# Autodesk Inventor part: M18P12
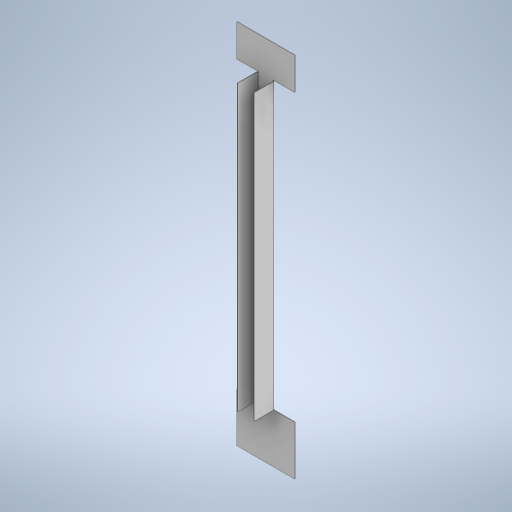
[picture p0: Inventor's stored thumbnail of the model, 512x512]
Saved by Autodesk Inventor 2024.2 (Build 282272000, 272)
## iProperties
Created: 2024-05
Part Number: M18P12
Material: Generic
Document SubType Name: Sheet Metal
Designer: Olivier St-Arneault
Density: 1 g/cm^3
Sheet Metal Rule: Default
Appearance: Default
Author: Olivier St-Arneault
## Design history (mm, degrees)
node "Face1"
  sketch "Sketch1"
    geometry: L1 (-26.987, 171.45)-(-26.987, 141.287); L2 (-26.987, 171.45)-(26.988, 171.45); L3 (26.988, 171.45)-(26.987, 141.287); L4 (26.987, 141.287)-(7.937, 141.287); L5 (-26.987, 141.287)-(-7.937, 141.287); L6 (-7.937, 141.287)-(-7.937, 140.875); L7 (7.937, 141.287)-(7.937, 140.875); L8 (-7.937, -125.413)-(-26.987, -125.413); L9 (7.938, -125.413)-(26.988, -125.413); L10 (-26.987, -125.413)-(-26.987, -171.45); L11 (-26.987, -171.45)-(26.988, -171.45); L12 (26.988, -171.45)-(26.988, -125.413); L13 (-39.175, 0)-(65.281, 0); L14 (0, 44.939)-(0, -395.251); L15 (-7.937, 140.875)-(-7.937, -125.413); L16 (7.938, -125.413)-(7.937, 140.875); 1 further point
    constraints: 32 end point, 6 vertical, 4 perpendicular, 3 horizontal, 2 point on line, 1 collinear, 1 other
    dimensions: "d0" = 30.1625 distance of L1.start L1.end; "d1" = 53.975 distance of L1.start L2.end; "d2" = 19.05 distance of L1.end L5.end; "d3" = 0.41275 distance of L5.end L6.end; "d11" = 342.9 distance between parallel lines of L2 L11; "d12" = 30.1625 distance between parallel lines of L4 L2; "d14" = 19.05 distance of L3.end L4.end; "d26" = 266.7 distance between parallel lines of L4 L9
node "Flange1"
body "Solid1"
face "Plate1" dims "d15" = 0.508 (= Thickness)
sketch "Sketch3"
  geometry: L1 (-266.192, 0)-(-0.508, 0); L2 (-0.508, 0)-(-0.508, 19.05); L3 (-0.508, 19.05)-(-266.192, 19.05); L4 (-266.192, 19.05)-(-266.192, 0)
  constraints: 8 end point
face "Plate2" dims "d15" = 0.508 (= Thickness), "d16" = 0.508 (= BendReliefWidth), "d17" = 0.254 (= BendReliefDepth), "d18" = 1.016 (= MinimumRemnant), "d19" = 0.508 (= TransitionRadius), "d20" = 19.05, "d21" = 90 deg, "d22" = 0.508 (= BendRadius), "d23" = 2.032 (= CornerReliefSize), "d24" = 0.508 (= GapSize), "d25" = 0.508 (= JacobiRadiusSize), "SeamGap" = 0.00508
bend "Bend1" dims "d15" = 0.508 (= Thickness), "d16" = 0.508 (= BendReliefWidth), "d17" = 0.254 (= BendReliefDepth), "d18" = 1.016 (= MinimumRemnant), "d19" = 0.508 (= TransitionRadius), "d20" = 19.05, "d21" = 90 deg, "d22" = 0.508 (= BendRadius), "SeamGap" = 0.00508
feature "Corner1" dims "d20" = 19.05, "d21" = 90 deg, "d23" = 2.032 (= CornerReliefSize), "d24" = 0.508 (= GapSize), "d25" = 0.508 (= JacobiRadiusSize)
other parameters: "Thickness" = 0.508 (derived), "BendRadius" = 0.508 (= Thickness), "BendReliefWidth" = 0.508 (= Thickness), "BendReliefDepth" = 0.254 (= 0.5 x Thickness), "CornerReliefSize" = 2.032 (= 4 x Thickness), "MinimumRemnant" = 1.016 (= 2 x Thickness), "TransitionRadius" = 0.508 (= BendRadius), "JacobiRadiusSize" = 0.508 (= BendRadius), "GapSize" = 0.508 (= Thickness)
